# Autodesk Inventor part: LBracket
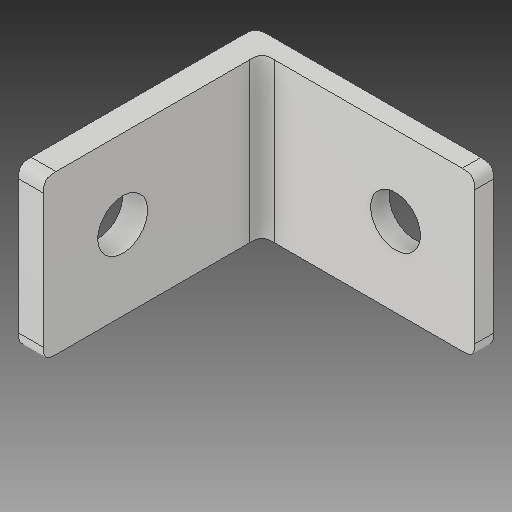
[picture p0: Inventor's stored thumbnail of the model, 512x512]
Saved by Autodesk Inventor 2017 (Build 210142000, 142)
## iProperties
Created: 2017-05
Part Number: LBracket
Material: Generic
Document SubType Name: Modeling
Designer: Savy
Density: 1 g/cm^3
Appearance: Default
Mass: 0.762887 g
Surface Area: 10.7679 cm^2
Volume: 0.762887 cm^3
Author: Savy
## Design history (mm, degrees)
feature "Base1"
body "Solid1"
